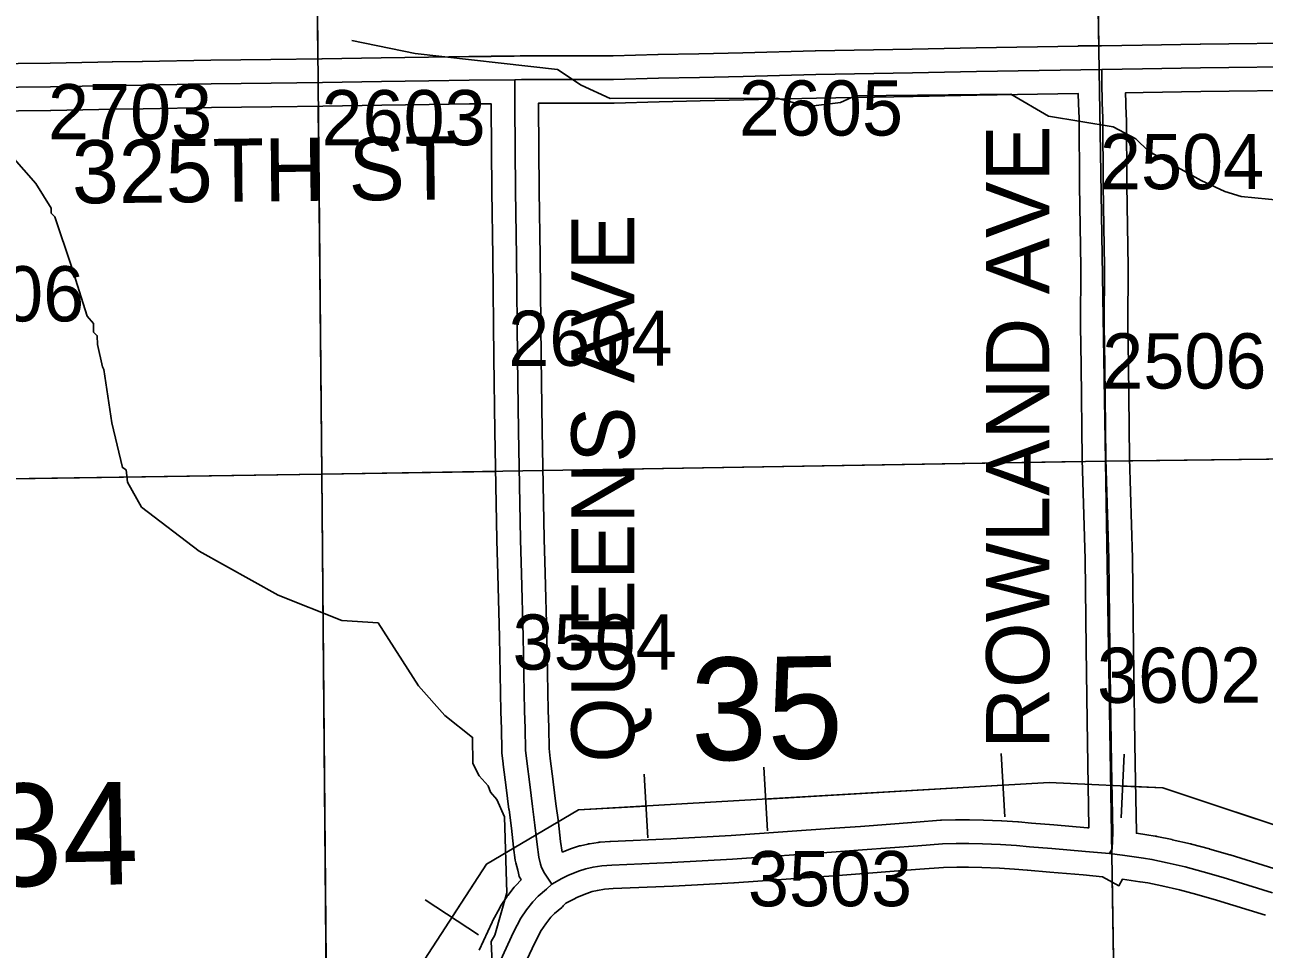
# Model space of a CAD drawing. Extents: x 23.6 to 68.7, y -63 to -29.
# Drawn here: x 48.415 to 49.986, y -57.182 to -56.01 of the extents above; entities that cross this region are included whole.
import ezdxf

# ---------------------------------------------------------------- set-up
doc = ezdxf.new("R2010")
doc.units = 0
for name, color, linetype in [('tdCoHydroRiver', 7, 'Continuous'), ('tdCoPipe', 7, 'Continuous'), ('tdCoSecRdNmbr', 7, 'Continuous'), ('tdCoSecRdTxt', 7, 'Continuous'), ('tdCoSecRteBand', 7, 'Continuous'), ('tdCoSecRteCL', 7, 'Continuous'), ('tdCoSectLine', 7, 'Continuous'), ('tdCoSectLinePart', 7, 'Continuous'), ('tdCoSectNmbr', 7, 'Continuous'), ('tdCoSurfAsphalt', 7, 'Continuous'), ('tdCoSurfEarth', 7, 'Continuous'), ('tdCoSurfGravel', 7, 'Continuous')]:
    doc.layers.add(name, color=color, linetype=linetype)

msp = doc.modelspace()

# ---------------------------------------------------------------- linework, layer by layer
at = {"layer": 'tdCoHydroRiver'}
for points in [[(50.0265, -56.2344), (49.9569, -56.2273), (49.9363, -56.2212), (49.9062, -56.2073), (49.8395, -56.1701), (49.8235, -56.1545), (49.7949, -56.139), (49.7127, -56.1257), (49.665, -56.0979), (49.4677, -56.1), (49.4489, -56.1081), (49.4079, -56.1133), (49.3683, -56.1027), (49.1568, -56.1034), (49.1203, -56.0865), (49.0901, -56.0663), (48.9099, -56.0462), (48.8292, -56.0297)], [(49.008, -57.218), (49.0059, -57.1722), (49.0106, -57.1643), (49.0258, -57.1105), (49.0231, -57.0142), (49.0134, -56.9922), (49.0054, -56.9828), (49.0022, -56.9749), (48.991, -56.9624), (48.9829, -56.9467), (48.9826, -56.9136), (48.9475, -56.8856), (48.914, -56.848), (48.8626, -56.7681), (48.8168, -56.7654), (48.7359, -56.7332), (48.6358, -56.6774), (48.5626, -56.6214), (48.5449, -56.59), (48.5431, -56.5743), (48.5384, -56.5712), (48.5251, -56.5145), (48.5149, -56.4467), (48.5133, -56.4436), (48.5067, -56.4152), (48.5066, -56.4042), (48.5018, -56.3995), (48.5017, -56.3885), (48.4937, -56.3791), (48.474, -56.3161), (48.4528, -56.2532), (48.448, -56.2485), (48.448, -56.2422), (48.4287, -56.2109), (48.3983, -56.1765)]]:
    msp.add_lwpolyline(points, dxfattribs=at)
at = {"layer": 'tdCoPipe'}
for p, q in [((49.6527, -56.9339), (49.6573, -57.0143)), ((49.8089, -56.9349), (49.8051, -57.0155)), ((49.3518, -56.9514), (49.3565, -57.032)), ((49.1999, -56.9603), (49.2046, -57.0407)), ((48.9226, -57.1197), (48.9902, -57.1637))]:
    msp.add_line(p, q, dxfattribs=at)
for points in [[(53.0685, -56.591), (50.7015, -56.6132), (50.7179, -57.2247), (50.5989, -57.2241), (49.8578, -56.9776), (49.7137, -56.9708), (49.1168, -57.0055), (49.0002, -57.0742), (48.9111, -57.2115), (48.8699, -57.2459), (48.815, -57.2528), (48.1221, -57.267), (48.1221, -57.267), (48.0398, -57.2807), (47.9849, -57.2876), (47.9163, -57.3083), (47.7174, -57.528), (47.6625, -57.5281), (46.0227, -57.536), (46.016, -57.7076)], [(49.655, -56.9742), (49.3542, -56.9917)], [(50.0955, -57.0567), (49.8578, -56.9776), (49.807, -56.9752)], [(49.2022, -57.0005), (49.1168, -57.0055), (49.0002, -57.0742), (48.9564, -57.1417)]]:
    msp.add_lwpolyline(points, dxfattribs=at)
at = {"layer": 'tdCoSecRteBand'}
for points in [[(48.3652, -56.0592), (48.4468, -56.0584), (48.5072, -56.0573), (48.5257, -56.0569), (48.5259, -56.0569), (48.526, -56.0569), (48.5637, -56.0562), (48.5637, -56.0562), (48.5638, -56.0562), (48.6505, -56.0548), (48.6506, -56.0548), (48.6507, -56.0548), (48.7269, -56.0539), (48.7915, -56.0528), (48.7916, -56.0528), (48.7917, -56.0528), (48.8665, -56.0518), (48.9266, -56.0509), (48.9266, -56.0509), (48.9266, -56.0509), (48.9778, -56.0501), (48.9779, -56.0501), (48.9781, -56.0501), (49.006, -56.0499), (49.006, -56.0496), (49.0352, -56.0496), (49.0428, -56.0492), (49.0437, -56.0492), (49.0446, -56.0492), (49.07, -56.0493), (49.1609, -56.049), (49.2176, -56.0476), (49.2176, -56.0476), (49.2176, -56.0476), (49.2694, -56.0464), (49.2695, -56.0464), (49.2695, -56.0464), (49.3251, -56.0451), (49.417, -56.0429), (49.4171, -56.0429), (49.4172, -56.0429), (49.5398, -56.0406), (49.6209, -56.0388), (49.621, -56.0388), (49.6211, -56.0388), (49.7502, -56.0369), (49.7502, -56.0365), (49.7799, -56.0365), (49.8315, -56.0354), (49.8316, -56.0354), (49.8317, -56.0354), (49.9053, -56.0343), (49.9054, -56.0343), (49.9054, -56.0343), (50.0486, -56.0327)], [(49.0959, -57.0592), (49.1057, -57.0552), (49.1067, -57.0548), (49.1078, -57.0545), (49.1169, -57.0515), (49.1182, -57.0511), (49.1195, -57.0508), (49.1287, -57.0488), (49.1296, -57.0485), (49.1306, -57.0484), (49.1418, -57.0466), (49.1431, -57.0464), (49.1443, -57.0463), (49.1567, -57.0454), (49.1572, -57.0454), (49.1576, -57.0454), (49.2338, -57.0422), (49.3103, -57.0381), (49.4416, -57.0286), (49.4416, -57.0286), (49.4416, -57.0286), (49.4746, -57.0263), (49.545, -57.021), (49.5759, -57.0186), (49.5766, -57.0186), (49.5772, -57.0186), (49.5949, -57.018), (49.5954, -57.0179), (49.5959, -57.0179), (49.6118, -57.0179), (49.6123, -57.0179), (49.6128, -57.018), (49.6302, -57.0186), (49.6303, -57.0186), (49.6304, -57.0186), (49.6531, -57.0194), (49.6534, -57.0195), (49.6537, -57.0195), (49.6737, -57.0207), (49.6742, -57.0207), (49.6746, -57.0207), (49.6911, -57.0222), (49.7196, -57.0245), (49.7196, -57.0245), (49.7196, -57.0245), (49.7621, -57.0281), (49.7622, -57.0281), (49.7624, -57.0281), (49.7636, -57.0282), (49.7637, -57.0278), (49.7641, -57.0279), (49.7627, -56.9478), (49.7627, -56.9477), (49.7627, -56.9476), (49.762, -56.8923), (49.7604, -56.8007), (49.7604, -56.8006), (49.7604, -56.8005), (49.7592, -56.6876), (49.7555, -56.561), (49.7555, -56.5607), (49.7555, -56.5605), (49.7541, -56.4421), (49.7534, -56.391), (49.7534, -56.3908), (49.7534, -56.3905), (49.7536, -56.317), (49.7529, -56.2653), (49.7523, -56.2134), (49.7523, -56.2134), (49.7523, -56.2134), (49.7515, -56.128), (49.7509, -56.1101), (49.7509, -56.11), (49.7509, -56.11), (49.7506, -56.0969), (49.6221, -56.0988), (49.541, -56.1005), (49.541, -56.1005), (49.541, -56.1005), (49.4184, -56.1029), (49.3265, -56.1051), (49.3265, -56.1051), (49.3265, -56.1051), (49.2709, -56.1063), (49.219, -56.1076), (49.162, -56.109), (49.1617, -56.109), (49.1614, -56.109), (49.0701, -56.1093), (49.0699, -56.1093), (49.0698, -56.1093), (49.0662, -56.1093), (49.0662, -56.1094), (49.066, -56.1094), (49.066, -56.1125), (49.067, -56.2202), (49.068, -56.303), (49.068, -56.303), (49.068, -56.303), (49.0696, -56.4315), (49.0709, -56.5243), (49.0732, -56.6616), (49.0745, -56.7053), (49.0745, -56.7053), (49.0745, -56.7054), (49.0766, -56.7846), (49.0766, -56.7847), (49.0766, -56.7848), (49.0784, -56.8792), (49.0791, -56.9007), (49.0791, -56.9009), (49.0791, -56.9012), (49.0796, -56.9277), (49.081, -56.9402), (49.0848, -56.9693), (49.0848, -56.9695), (49.0849, -56.9697), (49.0882, -56.9976), (49.0913, -57.0209), (49.0913, -57.0212), (49.0913, -57.0215), (49.094, -57.0455), (49.0959, -57.0592)], [(50.0493, -56.0927), (49.9061, -56.0943), (49.8327, -56.0954), (49.8107, -56.0959), (49.8107, -56.0961), (49.8106, -56.0961), (49.8109, -56.1084), (49.8114, -56.1266), (49.8114, -56.1269), (49.8115, -56.1271), (49.8123, -56.2127), (49.8129, -56.2646), (49.8136, -56.3165), (49.8136, -56.3167), (49.8136, -56.317), (49.8134, -56.3904), (49.8141, -56.4413), (49.8141, -56.4413), (49.8141, -56.4414), (49.8155, -56.5595), (49.8191, -56.6862), (49.8192, -56.6864), (49.8192, -56.6867), (49.8204, -56.7997), (49.822, -56.8914), (49.822, -56.8915), (49.822, -56.8915), (49.8227, -56.9468), (49.8242, -57.0337), (49.8242, -57.0345), (49.8242, -57.0351), (49.8376, -57.0371), (49.848, -57.0386), (49.8491, -57.0387), (49.8502, -57.039), (49.8694, -57.0431), (49.8696, -57.0431), (49.8698, -57.0432), (49.8928, -57.0485), (49.8934, -57.0486), (49.8939, -57.0488), (49.9169, -57.055), (49.9172, -57.055), (49.9175, -57.0551), (49.9428, -57.0625), (49.943, -57.0626), (49.9433, -57.0626), (50.0054, -57.0818)], [(48.9908, -57.1834), (49.0072, -57.148), (49.0075, -57.1472), (49.0079, -57.1465), (49.0174, -57.1288), (49.0181, -57.1275), (49.0189, -57.1263), (49.026, -57.1156), (49.0265, -57.1148), (49.0272, -57.114), (49.0351, -57.1036), (49.0361, -57.1024), (49.0372, -57.1012), (49.044, -57.0941), (49.0441, -57.094), (49.0437, -57.0934), (49.0417, -57.0898), (49.0407, -57.0858), (49.0397, -57.0817), (49.0374, -57.0726), (49.0369, -57.0709), (49.0367, -57.0693), (49.0345, -57.0533), (49.0345, -57.0529), (49.0344, -57.0525), (49.0317, -57.0284), (49.0287, -57.0053), (49.0287, -57.0051), (49.0286, -57.0049), (49.0253, -56.9769), (49.0215, -56.9477), (49.0214, -56.9474), (49.0214, -56.947), (49.0198, -56.9329), (49.0197, -56.9315), (49.0197, -56.9302), (49.0192, -56.9025), (49.0184, -56.8811), (49.0184, -56.8809), (49.0184, -56.8806), (49.0166, -56.786), (49.0145, -56.707), (49.0132, -56.6632), (49.0132, -56.663), (49.0132, -56.6628), (49.0109, -56.5253), (49.0109, -56.5252), (49.0109, -56.5252), (49.0096, -56.4323), (49.0096, -56.4322), (49.0096, -56.4322), (49.008, -56.3037), (49.007, -56.2209), (49.007, -56.2209), (49.007, -56.2208), (49.006, -56.113), (49.006, -56.1128), (49.006, -56.1127), (49.006, -56.1099), (48.9787, -56.1101), (48.9275, -56.1109), (48.8674, -56.1118), (48.8673, -56.1118), (48.8673, -56.1118), (48.7925, -56.1128), (48.7278, -56.1139), (48.7278, -56.1139), (48.7277, -56.1139), (48.6515, -56.1148), (48.5647, -56.1162), (48.5271, -56.1168), (48.5086, -56.1173), (48.5085, -56.1173), (48.5084, -56.1173), (48.4478, -56.1184), (48.4476, -56.1184), (48.4475, -56.1184), (48.3657, -56.1192)], [(49.9878, -57.1391), (49.9258, -57.12), (49.901, -57.1128), (49.8788, -57.1068), (49.8565, -57.1017), (49.8387, -57.0979), (49.8292, -57.0965), (49.8289, -57.0965), (49.8287, -57.0965), (49.8068, -57.0931), (49.8021, -57.1017), (49.7812, -57.0902), (49.7569, -57.0879), (49.7146, -57.0843), (49.686, -57.082), (49.6859, -57.082), (49.6858, -57.082), (49.6698, -57.0805), (49.6505, -57.0794), (49.6281, -57.0785), (49.6113, -57.0779), (49.5964, -57.0779), (49.5798, -57.0785), (49.5495, -57.0808), (49.5495, -57.0808), (49.5495, -57.0808), (49.479, -57.0861), (49.479, -57.0861), (49.4789, -57.0861), (49.4459, -57.0885), (49.3144, -57.0979), (49.3141, -57.0979), (49.3138, -57.098), (49.2368, -57.1021), (49.2367, -57.1021), (49.2365, -57.1021), (49.1606, -57.1053), (49.1499, -57.1061), (49.1409, -57.1075), (49.1341, -57.1091), (49.1272, -57.1113), (49.1157, -57.1159), (49.1099, -57.1189), (49.1009, -57.1238), (49.0975, -57.1273), (49.0965, -57.1282), (49.0955, -57.1291), (49.0862, -57.1369), (49.0817, -57.1416), (49.0753, -57.1498), (49.0696, -57.1583), (49.0613, -57.174), (49.0451, -57.2089)]]:
    msp.add_lwpolyline(points, dxfattribs=at)
at = {"layer": 'tdCoSecRteCL'}
for points in [[(49.036, -56.0796), (49.0444, -56.0792), (49.0699, -56.0793), (49.1613, -56.079), (49.2183, -56.0776), (49.2702, -56.0764), (49.3258, -56.0751), (49.4177, -56.0729), (49.5404, -56.0706), (49.6216, -56.0688), (49.7802, -56.0665)], [(49.7802, -56.0665), (49.8321, -56.0654), (49.9057, -56.0643), (50.0489, -56.0627)], [(49.7902, -57.0609), (49.7935, -57.0549), (49.7942, -57.0343), (49.7927, -56.9472), (49.792, -56.8919), (49.7904, -56.8001), (49.7892, -56.687), (49.7855, -56.5601), (49.7841, -56.4417), (49.7834, -56.3906), (49.7836, -56.3169), (49.7829, -56.265), (49.7823, -56.2131), (49.7815, -56.1274), (49.7809, -56.1092), (49.7802, -56.0817), (49.7802, -56.0665)], [(48.2867, -56.0929), (48.2976, -56.0909), (48.3015, -56.0903), (48.3128, -56.0897), (48.3654, -56.0892), (48.4472, -56.0884), (48.5078, -56.0873), (48.5265, -56.0868), (48.5642, -56.0862), (48.651, -56.0848), (48.7273, -56.0839), (48.792, -56.0828), (48.8669, -56.0818), (48.9271, -56.0809), (48.9783, -56.0801), (49.036, -56.0796)], [(49.0828, -57.0996), (49.0739, -57.0857), (49.0698, -57.0785), (49.0688, -57.0744), (49.0664, -57.0652), (49.0642, -57.0492), (49.0615, -57.0248), (49.0584, -57.0013), (49.0551, -56.9732), (49.0512, -56.9438), (49.0497, -56.9296), (49.0491, -56.9017), (49.0484, -56.8801), (49.0466, -56.7854), (49.0445, -56.7061), (49.0432, -56.6623), (49.0409, -56.5247), (49.0396, -56.4319), (49.038, -56.3034), (49.037, -56.2205), (49.036, -56.1127), (49.036, -56.0796)], [(49.0828, -57.0996), (49.0958, -57.0925), (49.1031, -57.0886), (49.117, -57.083), (49.1261, -57.0801), (49.1353, -57.078), (49.1465, -57.0763), (49.1589, -57.0754), (49.2352, -57.0721), (49.3122, -57.068), (49.4437, -57.0586), (49.4768, -57.0562), (49.5472, -57.0509), (49.5782, -57.0485), (49.5959, -57.0479), (49.6118, -57.0479), (49.6292, -57.0485), (49.6519, -57.0494), (49.672, -57.0506), (49.6885, -57.0521), (49.7171, -57.0544), (49.7596, -57.058), (49.7902, -57.0609)], [(49.7902, -57.0609), (49.8065, -57.0627), (49.8333, -57.0668), (49.8439, -57.0683), (49.8631, -57.0724), (49.8861, -57.0777), (49.9091, -57.0839), (49.9344, -57.0913), (49.9967, -57.1105)], [(49.0179, -57.1963), (49.0344, -57.1606), (49.0439, -57.1429), (49.0509, -57.1323), (49.0589, -57.122), (49.0657, -57.1149), (49.0763, -57.106), (49.0828, -57.0996)]]:
    msp.add_lwpolyline(points, dxfattribs=at)
at = {"layer": 'tdCoSectLine'}
for points in [[(49.7688, -55.5715), (49.7852, -56.563)], [(48.7819, -55.5882), (48.7912, -56.5798)], [(49.7852, -56.563), (50.7851, -56.5511)], [(48.7912, -56.5798), (49.7852, -56.563)], [(49.7852, -56.563), (49.8013, -57.5613)], [(47.7923, -56.5945), (48.7912, -56.5798)], [(48.7912, -56.5798), (48.8, -57.5731)]]:
    msp.add_lwpolyline(points, dxfattribs=at)
at = {"layer": 'tdCoSectLinePart'}
for points in [[(49.7688, -55.5715), (49.7765, -56.0363)], [(48.7819, -55.5882), (48.7863, -56.0529)], [(48.7868, -56.113), (48.7912, -56.5798)], [(49.8152, -56.5627), (50.7552, -56.5515)], [(48.7912, -56.5798), (49.0117, -56.5761)], [(49.0716, -56.5751), (49.7552, -56.5636)], [(48.316, -56.5868), (48.7912, -56.5798)], [(48.7912, -56.5798), (48.7975, -57.2933)], [(49.7937, -57.0917), (49.8013, -57.5613)]]:
    msp.add_lwpolyline(points, dxfattribs=at)
at = {"layer": 'tdCoSurfAsphalt'}
msp.add_lwpolyline([(49.0179, -57.1963), (49.0344, -57.1606), (49.0439, -57.1429), (49.0509, -57.1323), (49.0589, -57.122), (49.0657, -57.1149), (49.0763, -57.106), (49.0828, -57.0996), (49.0958, -57.0925), (49.1031, -57.0886), (49.117, -57.083), (49.1261, -57.0801), (49.1353, -57.078), (49.1465, -57.0763), (49.1589, -57.0754), (49.2352, -57.0721), (49.3122, -57.068), (49.4437, -57.0586), (49.4768, -57.0562), (49.5472, -57.0509), (49.5782, -57.0485), (49.5959, -57.0479), (49.6118, -57.0479), (49.6292, -57.0485), (49.6519, -57.0494), (49.672, -57.0506), (49.6885, -57.0521), (49.7171, -57.0544), (49.7596, -57.058), (49.7902, -57.0609), (49.8065, -57.0627), (49.8333, -57.0668), (49.8439, -57.0683), (49.8631, -57.0724), (49.8861, -57.0777), (49.9091, -57.0839), (49.9344, -57.0913), (49.9967, -57.1105)], dxfattribs=at)
at = {"layer": 'tdCoSurfEarth'}
msp.add_lwpolyline([(49.7902, -57.0609), (49.7935, -57.0549), (49.7942, -57.0343), (49.7927, -56.9472), (49.792, -56.8919), (49.7904, -56.8001), (49.7892, -56.687), (49.7855, -56.5601), (49.7841, -56.4417), (49.7834, -56.3906), (49.7836, -56.3169), (49.7829, -56.265)], dxfattribs=at)
at = {"layer": 'tdCoSurfGravel'}
for points in [[(48.3654, -56.0892), (48.4472, -56.0884), (48.5078, -56.0873), (48.5265, -56.0868), (48.5642, -56.0862), (48.651, -56.0848), (48.7273, -56.0839), (48.792, -56.0828), (48.8669, -56.0818), (48.9271, -56.0809), (48.9783, -56.0801), (49.036, -56.0796), (49.0444, -56.0792), (49.0699, -56.0793), (49.1613, -56.079), (49.2183, -56.0776), (49.2702, -56.0764), (49.3258, -56.0751), (49.4177, -56.0729), (49.5404, -56.0706), (49.6216, -56.0688), (49.7802, -56.0665), (49.8321, -56.0654), (49.9057, -56.0643), (50.0489, -56.0627)], [(49.7829, -56.265), (49.7823, -56.2131), (49.7815, -56.1274), (49.7809, -56.1092), (49.7802, -56.0817), (49.7802, -56.0665)], [(49.0828, -57.0996), (49.0739, -57.0857), (49.0698, -57.0785), (49.0688, -57.0744), (49.0664, -57.0652), (49.0642, -57.0492), (49.0615, -57.0248), (49.0584, -57.0013), (49.0551, -56.9732), (49.0512, -56.9438), (49.0497, -56.9296), (49.0491, -56.9017), (49.0484, -56.8801), (49.0466, -56.7854), (49.0445, -56.7061), (49.0432, -56.6623), (49.0409, -56.5247), (49.0396, -56.4319), (49.038, -56.3034), (49.037, -56.2205), (49.036, -56.1127), (49.036, -56.0796)]]:
    msp.add_lwpolyline(points, dxfattribs=at)

# ---------------------------------------------------------------- texts
at = {"layer": 'tdCoSecRdNmbr'}
for s, rotation, p in [('2703', 0.0375, (48.4441, -56.155)), ('2605', 0.0382, (49.3201, -56.1503)), ('2603', 0.0378, (48.7909, -56.1626)), ('2504', 0.0385, (49.778, -56.2183)), ('2706', 0.0374, (48.2818, -56.386)), ('2604', 0.0379, (49.0277, -56.4423)), ('2506', 0.0385, (49.7809, -56.4711)), ('3504', 0.0379, (49.0332, -56.8276)), ('3602', 0.0385, (49.7743, -56.8697)), ('3503', 0.0381, (49.3316, -57.1277))]:
    msp.add_text(s, height=0.07, rotation=rotation, dxfattribs=at).set_placement(p)
at = {"layer": 'tdCoSecRdTxt'}
for s, rotation, p in [('325TH ST', 0.6278, (48.4748, -56.2364)), ('ROWLAND AVE', 90, (49.7137, -56.928)), ('QUEENS AVE', 90, (49.1878, -56.9457))]:
    msp.add_text(s, height=0.08, rotation=rotation, dxfattribs=at).set_placement(p)
at = {"layer": 'tdCoSectNmbr'}
for s, rotation, p in [('35', 1.038, (49.2599, -56.9431)), ('34', 1.0373, (48.3666, -57.103))]:
    msp.add_text(s, height=0.13, rotation=rotation, dxfattribs=at).set_placement(p)

doc.saveas('drawing.dxf')
